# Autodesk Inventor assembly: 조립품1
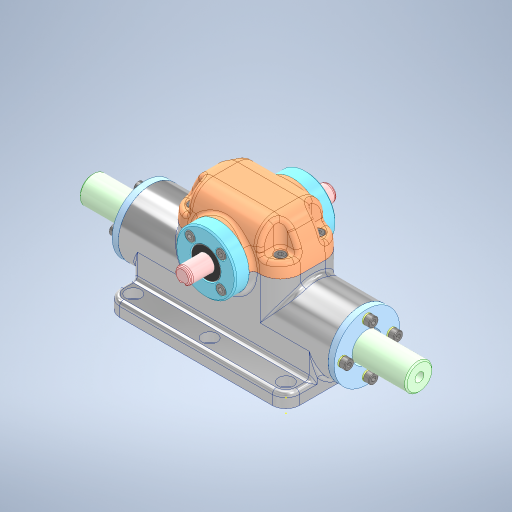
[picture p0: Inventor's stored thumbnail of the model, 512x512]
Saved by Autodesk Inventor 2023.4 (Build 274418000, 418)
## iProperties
Created: 2024-06
Part Number: 조립품1
Document SubType Name: Assembly
Designer: EDU-001
Author: EDU-001
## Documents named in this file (13)
- C:\Users\EDU-001\Desktop\740604v1014\조립품1.iam
- C:\Users\EDU-001\Desktop\부품1.ipt
- C:\Users\EDU-001\Desktop\740604v1014\깊은 홈 볼 베어링 6901.ipt
- C:\Users\EDU-001\Desktop\740604v1014\랙.ipt
- C:\Users\EDU-001\Desktop\740604v1014\베어링 커버.ipt
- C:\Users\EDU-001\Desktop\740604v1014\부시 커버.ipt
- C:\Users\EDU-001\Desktop\740604v1014\스프링 와셔 M4.ipt
- C:\Users\EDU-001\Desktop\740604v1014\오일레스 부시.ipt
- C:\Users\EDU-001\Desktop\740604v1014\오일실 12 22 7.ipt
- C:\Users\EDU-001\Desktop\740604v1014\윗커버.ipt
- C:\Users\EDU-001\Desktop\740604v1014\육각 소켓 머리 볼트 M4x10.ipt
- C:\Users\EDU-001\Desktop\740604v1014\칼라.ipt
- C:\Users\EDU-001\Desktop\740604v1014\피니언.ipt
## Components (1 placed, 1 different names)
1. 피니언:1
## Named parameters: d64_d60 = 0, d65_d61 = 0, d66_d60 = 0, d67_d61 = 0, d68_d60 = 0, d69_d61 = 0
